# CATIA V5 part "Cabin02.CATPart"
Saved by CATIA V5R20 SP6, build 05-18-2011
Part number: Cabin02
Bounding box of the stored display mesh (mm): x -721.019 to -578.019, y 0 to 20, z 395 to 635
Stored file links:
  E:\#01 CATIA Lecture Materials\#06 DMU\#01 DMU KIN Page01 EX01\#01 CATPart\Cabin02.CATPart
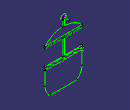
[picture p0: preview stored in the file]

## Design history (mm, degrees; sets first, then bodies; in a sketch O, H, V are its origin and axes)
AxisSystem1: origin (-649.5191, 0, 625), X (1, 0, 0), Y (0, 1, 0), Z (0, 0, 1)
Set1
  DatumCurve1 "Curve.1 ( *CRV88 - wsp *MASTER -  )"
  DatumCurve2 "Curve.2 ( *CRV89 - wsp *MASTER -  )"
  DatumCurve3 "Curve.3 ( *CRV90 - wsp *MASTER -  )"
  DatumCurve4 "Curve.4 ( *CRV91 - wsp *MASTER -  )"
  DatumCurve5 "Curve.5 ( *CRV92 - wsp *MASTER -  )"
  DatumCurve6 "Curve.6 ( *CRV93 - wsp *MASTER -  )"
  DatumCurve7 "Curve.7 ( *CRV94 - wsp *MASTER -  )"
  DatumCurve8 "Curve.8 ( *CRV95 - wsp *MASTER -  )"
  DatumCurve9 "Curve.9 ( *CRV96 - wsp *MASTER -  )"
  DatumCurve10 "Curve.10 ( *CRV97 - wsp *MASTER -  )"
  DatumCurve11 "Curve.11 ( *CRV98 - wsp *MASTER -  )"
  DatumCurve12 "Curve.12 ( *CRV99 - wsp *MASTER -  )"
  DatumCurve13 "Curve.13 ( *CRV100 - wsp *MASTER -  )"
  DatumCurve14 "Curve.14 ( *CRV101 - wsp *MASTER -  )"
  DatumCurve15 "Curve.15 ( *CRV102 - wsp *MASTER -  )"
  DatumCurve16 "Curve.16 ( *CRV103 - wsp *MASTER -  )"
  DatumCurve17 "Curve.17 ( *CRV104 - wsp *MASTER -  )"
  Line1 "Line.1 ( *LN173 - wsp *MASTER -  )": stored without definition
  Line2 "Line.2 ( *LN174 - wsp *MASTER -  )": stored without definition
  Line3 "Line.3 ( *LN175 - wsp *MASTER -  )": stored without definition
  Line4 "Line.4 ( *LN176 - wsp *MASTER -  )": stored without definition
  Line5 "Line.5 ( *LN177 - wsp *MASTER -  )": stored without definition
  Line6 "Line.6 ( *LN178 - wsp *MASTER -  )": stored without definition
  Line7 "Line.7 ( *LN179 - wsp *MASTER -  )": stored without definition
  Line8 "Line.8 ( *LN180 - wsp *MASTER -  )": stored without definition
  Line9 "Line.9 ( *LN181 - wsp *MASTER -  )": stored without definition
  Line10 "Line.10 ( *LN182 - wsp *MASTER -  )": stored without definition
  Line11 "Line.11 ( *LN183 - wsp *MASTER -  )": stored without definition
  Line12 "Line.12 ( *LN184 - wsp *MASTER -  )": stored without definition
  Line13 "Line.13 ( *LN185 - wsp *MASTER -  )": stored without definition
  Line14 "Line.14 ( *LN186 - wsp *MASTER -  )": stored without definition
  Line15 "Line.15 ( *LN187 - wsp *MASTER -  )": stored without definition
  Line16 "Line.16 ( *LN188 - wsp *MASTER -  )": stored without definition
  Line17 "Line.17 ( *LN189 - wsp *MASTER -  )": stored without definition
  Line18 "Line.18 ( *LN190 - wsp *MASTER -  )": stored without definition
  Line19 "Line.19 ( *LN191 - wsp *MASTER -  )": stored without definition
  Line20 "Line.20 ( *LN192 - wsp *MASTER -  )": stored without definition
  Line21 "Line.21 ( *LN193 - wsp *MASTER -  )": stored without definition
  Line22 "Line.22 ( *LN194 - wsp *MASTER -  )": stored without definition
  Line23 "Line.23 ( *LN195 - wsp *MASTER -  )": stored without definition
  Line24 "Line.24 ( *LN196 - wsp *MASTER -  )": stored without definition
  Line25 "Line.25 ( *LN197 - wsp *MASTER -  )": stored without definition
  Line26 "Line.26 ( *LN198 - wsp *MASTER -  )": stored without definition
  Line27 "Line.27 ( *LN199 - wsp *MASTER -  )": stored without definition
  Line28 "Line.28 ( *LN200 - wsp *MASTER -  )": stored without definition
  Line29 "Line.29 ( *LN201 - wsp *MASTER -  )": stored without definition
  Line30 "Line.30 ( *LN202 - wsp *MASTER -  )": stored without definition
  Line31: stored without definition
  Point1: type OnCurve, Support Line25, Ratio 1
  Point2 "Point.6 ( PT6 - wsp *MASTER -  )": stored without definition
Body1 (main body)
